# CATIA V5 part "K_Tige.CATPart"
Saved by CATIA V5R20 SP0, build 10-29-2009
Part number: Tige
Property "Longueur Tige": 2320 mm
Property "Diamètre joint": 20 mm
Bounding box of the stored display mesh (mm): x -1180 to 1180, y -10 to 10, z -19.89 to 19.89
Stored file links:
  C:\Users\thinkmotion1\Desktop\Khaled_IAO_Pack2\Problemes\IAO_2010_1405_jpalas\IAO_PALAS\Khaled_Palas\K_Tige.CATPart
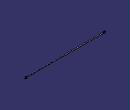
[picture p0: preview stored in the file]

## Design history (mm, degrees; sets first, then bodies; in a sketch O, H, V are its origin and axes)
Body1 (main body)
  Sketch1 on xy-plane, origin (0, 0, 0), H (1, 0, 0), V (0, 1, 0)
    line L1 (0, 0) -> (0, 10)
    line L2 (0, 10) -> (1120, 10)
    line L3 (0, 0) -> (1180, 0)
    line L4 (1120, 10) -> (1120, 20)
    line L5 (1120, 20) -> (1160, 20)
    arc A1 centre (1160, 0) radius 20 from (1180, 0) to (1160, 20) ccw
    distance L2 L3 = 10
    length L5 = 40
    length L4 = 10
    radius A1 = 20
    length L3 = 1180
    vertical: L1 V, L4 V
    horizontal: L2 H, L3 H, L5 H
    tangency: A1 L5
  Shaft1: profile Sketch1, axis Sketch1.L3, angle 360
  Sketch2 on face of Shaft1 from Sketch1.L4, origin (1120, 10, 0), H (0, 1, 0), V (0, 0, 1)
    line L1 (10, 20) -> (0, 20)
    line L2 (0, 20) -> (0, -20)
    line L3 (0, -20) -> (10, -20)
    line L4 (10, -20) -> (10, 20)
    reference projected circle E1 centre (-10, 0) radius 10 from edge [face of Shaft1 from Sketch1.L2 | face of Shaft1 from Sketch1.L4]
    reference projected circle E2 centre (-10, 0) radius 20 from edge [face of Shaft1 from Sketch1.L4 | face of Shaft1 from Sketch1.L5]
    reference projected circle E3 centre (-10, 0) radius 20 from edge [face of Shaft1 from Sketch1.L4 | face of Shaft1 from Sketch1.L5]
    reference projected circle E4 centre (-10, 0) radius 20 from edge [face of Shaft1 from Sketch1.L4 | face of Shaft1 from Sketch1.L5]
    line L5 (-20, 20) -> (-30, 20)
    line L6 (-30, 20) -> (-30, -20)
    line L7 (-30, -20) -> (-20, -20)
    line L8 (-20, -20) -> (-20, 20)
    reference projected circle E5 centre (-10, 0) radius 10 from edge [face of Shaft1 from Sketch1.L2 | face of Shaft1 from Sketch1.L4]
    reference projected circle E6 centre (-10, 0) radius 20 from edge [face of Shaft1 from Sketch1.L4 | face of Shaft1 from Sketch1.L5]
    reference projected circle E7 centre (-10, 0) radius 20 from edge [face of Shaft1 from Sketch1.L4 | face of Shaft1 from Sketch1.L5]
    reference projected circle E8 centre (-10, 0) radius 20 from edge [face of Shaft1 from Sketch1.L4 | face of Shaft1 from Sketch1.L5]
    horizontal: L1 H, L3 H, L5 H, L7 H
    vertical: L2 V, L4 V, L6 V, L8 V
    tangency: L2 E1, L3 E2, E3 L1, L4 E4, E5 L8, L6 E6, L7 E7, L5 E8
  Pocket1: profile Sketch2, direction (1, 0, 0), length 60
  Sketch3 on face of Pocket1 from Sketch2.L2, origin (477.1797, 10, -2.6472), H (1, 0, 0), V (0, 0, -1)
    point P1 (682.8203, -2.6472)
    reference projected arc E1 centre (682.8203, -2.6472) radius 17.3205 from (682.8203, -19.9677) to (682.8203, 14.6733) ccw from edge [face of Shaft1 from Sketch1.A1 | face of Pocket1 from Sketch2.L2]
    concentricity: P1 E1
  Hole1: placed by Sketch3, at (1160, 10, 0) direction (0, -1, 0), diameter 20, through (limit type 3)
  Mirror1: of Shaft1, Sketch1, Pocket1, Sketch2, Hole1, about face of Shaft1 from Sketch1.L1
